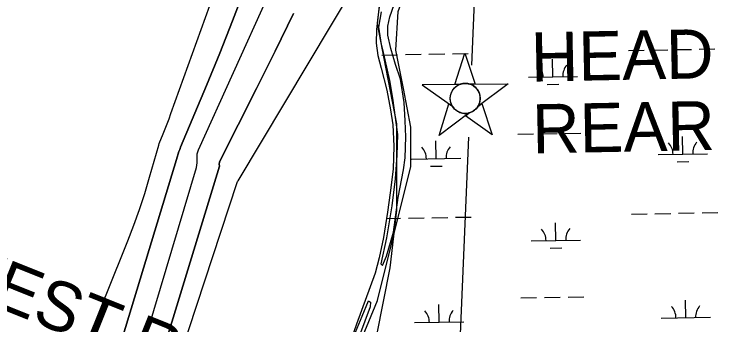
# Model space of a CAD drawing. Extents: x 3925854 to 3964121, y 224593 to 250589.
# Drawn here: x 3942841 to 3944269, y 234463 to 235095 of the extents above; entities that cross this region are included whole.
import ezdxf

# ---------------------------------------------------------------- set-up
doc = ezdxf.new("R2010")
doc.units = 0
for name, color, linetype in [('V-CHAN-NAID', 7, 'Continuous'), ('V-RIVR-EDGE', 7, 'Continuous'), ('V-RIVR-JETY', 7, 'Continuous'), ('V-RIVR-RANG', 7, 'Continuous'), ('V-RRAP-FSHR', 7, 'Continuous'), ('V-TOPO-DPTH', 7, 'Continuous'), ('V-TOPO-MAJR', 7, 'Continuous'), ('V-TOPO-MINR', 7, 'Continuous'), ('V-WETL-SWMP', 7, 'Continuous')]:
    doc.layers.add(name, color=color, linetype=linetype)

msp = doc.modelspace()

# ---------------------------------------------------------------- linework, layer by layer
at = {"layer": 'V-CHAN-NAID'}
for points in [[(3943747.738, 234951.96), (3943738.152, 234951.841), (3943758.037, 235015.724), (3943779.5, 234952.353), (3943769.913, 234952.235), (3943768.325, 234952.782), (3943766.219, 234953.361), (3943764.17, 234953.772), (3943762.129, 234954.04), (3943760.96, 234954.131), (3943759.424, 234954.183), (3943757.703, 234954.147), (3943756.334, 234954.05), (3943754.432, 234953.812), (3943753.071, 234953.567), (3943751.295, 234953.148), (3943749.773, 234952.698), (3943748.748, 234952.347)], [(3943747.738, 234951.96), (3943671.251, 234951.012), (3943733.689, 234906.82), (3943732.539, 234908.707), (3943731.697, 234910.319), (3943730.834, 234912.271), (3943730.098, 234914.311), (3943729.708, 234915.626), (3943729.315, 234917.245), (3943729.043, 234918.685), (3943728.824, 234920.279), (3943728.681, 234922.013), (3943728.638, 234923.593), (3943728.705, 234925.669), (3943728.856, 234927.29), (3943729.205, 234929.5), (3943729.649, 234931.432), (3943730.215, 234933.331), (3943730.837, 234935.022), (3943731.533, 234936.624), (3943732.317, 234938.175), (3943733.344, 234939.932), (3943734.346, 234941.422), (3943735.321, 234942.71), (3943736.301, 234943.875), (3943737.583, 234945.238), (3943738.615, 234946.223), (3943740.305, 234947.653), (3943741.5, 234948.546), (3943743.165, 234949.649), (3943744.878, 234950.628), (3943746.31, 234951.34)], [(3943769.913, 234952.235), (3943846.401, 234953.181), (3943785.077, 234907.456), (3943785.959, 234908.963), (3943786.901, 234910.829), (3943787.585, 234912.427), (3943788.286, 234914.396), (3943788.796, 234916.191), (3943789.162, 234917.838), (3943789.484, 234919.855), (3943789.639, 234921.431), (3943789.72, 234923.639), (3943789.65, 234925.7), (3943789.419, 234927.916), (3943789.118, 234929.668), (3943788.584, 234931.89), (3943787.902, 234934.017), (3943787.114, 234935.984), (3943786.438, 234937.415), (3943785.394, 234939.311), (3943784.298, 234941.012), (3943783.052, 234942.69), (3943781.761, 234944.204), (3943780.462, 234945.545), (3943778.801, 234947.045), (3943777.031, 234948.422), (3943775.325, 234949.566), (3943773.416, 234950.661), (3943771.93, 234951.394)], [(3943767.301, 234894.202), (3943705.977, 234848.477), (3943725.862, 234912.359), (3943733.689, 234906.82), (3943734.342, 234905.869), (3943735.761, 234904.037), (3943737.002, 234902.645), (3943738.497, 234901.171), (3943739.91, 234899.947), (3943741.386, 234898.82), (3943742.808, 234897.86), (3943744.506, 234896.857), (3943746.237, 234895.98), (3943748.044, 234895.204), (3943749.5, 234894.676), (3943751.138, 234894.179), (3943753.375, 234893.658), (3943754.912, 234893.401), (3943756.942, 234893.184), (3943758.481, 234893.11), (3943760.342, 234893.124), (3943762.029, 234893.235), (3943763.735, 234893.444), (3943765.631, 234893.792)], [(3943785.077, 234907.456), (3943792.763, 234913.188), (3943814.225, 234849.817), (3943759.614, 234888.471), (3943767.301, 234894.202), (3943768.957, 234894.71), (3943770.558, 234895.301), (3943772.698, 234896.257), (3943774.415, 234897.175), (3943776.259, 234898.325), (3943777.974, 234899.571), (3943779.502, 234900.846), (3943780.766, 234902.038), (3943782.122, 234903.485), (3943783.298, 234904.91), (3943784.389, 234906.404)]]:
    msp.add_lwpolyline(points, close=True, dxfattribs=at)
msp.add_circle((3943759.178, 234923.643), 30.541, dxfattribs=at)
at = {"layer": 'V-RIVR-EDGE'}
msp.add_lwpolyline([(3944040.446, 236067.646), (3944007.385, 235995.227), (3943991.642, 235945.636), (3943960.942, 235890.535), (3943855.463, 235692.957), (3943812.956, 235631.558), (3943768.875, 235583.541), (3943727.155, 235505.612), (3943670.48, 235374.156), (3943636.632, 235260.018), (3943585.466, 235124.626), (3943579.956, 235075.035), (3943597.274, 234983.724), (3943619.314, 234871.947), (3943619.314, 234696.41), (3943605.932, 234579.123), (3943578.382, 234442.157)], dxfattribs=at)
at = {"layer": 'V-RIVR-JETY'}
for points in [[(3943587.93, 235099.563), (3943582.437, 235068.37), (3943587.831, 235033.121), (3943590.822, 235022.92), (3943605.227, 234959.805), (3943611.009, 234924.162), (3943621.361, 234850.157), (3943619.631, 234807.971), (3943616.649, 234759.937), (3943610.06, 234705.306), (3943599.036, 234640.184), (3943587.395, 234587.575), (3943590.86, 234583.62), (3943598.93, 234602.665), (3943613.253, 234651.329), (3943622.404, 234722.34), (3943633.303, 234778.084), (3943637.151, 234803.047), (3943638.104, 234845.244), (3943636.584, 234878.094), (3943634.733, 234915.249), (3943627.542, 234962.635), (3943617.392, 234992.866), (3943608.047, 235025.036), (3943601.762, 235052.088), (3943601.614, 235070.461), (3943605.776, 235089.554), (3943614.705, 235114.452)], [(3943535.585, 234448.071), (3943549.698, 234480.714), (3943562.616, 234511.809), (3943566.493, 234509.413), (3943565.973, 234499.648), (3943543.703, 234441.319)]]:
    msp.add_lwpolyline(points, dxfattribs=at)
at = {"layer": 'V-RIVR-RANG'}
for points in [[(3943812.557, 235958.749), (3943771.737, 234990.891)], [(3943765.567, 234844.599), (3943658.865, 232314.647)]]:
    msp.add_lwpolyline(points, dxfattribs=at)
at = {"layer": 'V-RRAP-FSHR'}
msp.add_lwpolyline([(3943550.3, 234438.974), (3943580.758, 234512.837), (3943648.153, 234785.105), (3943648.444, 234864.923), (3943633.272, 234943.444), (3943617.876, 235021.948), (3943622.994, 235100.327), (3943650.171, 235175.566), (3943678.906, 235250.224), (3943708.387, 235324.593), (3943738.82, 235398.878), (3943769.606, 235472.399), (3943805.37, 235543.862), (3943853.205, 235607.915), (3943894.849, 235676.646), (3943933.18, 235746.524), (3943970.3, 235817.305), (3944005.82, 235888.983), (3944041.119, 235960.773), (3944076.417, 236032.566), (3944110.874, 236104.758)], dxfattribs=at)
at = {"layer": 'V-TOPO-DPTH'}
for points in [[(3943310.805, 235147.024), (3943285.653, 235081.057), (3943259.501, 235015.481), (3943232.683, 234950.164), (3943179.881, 234824.293), (3943178.983, 234822.099), (3943178.111, 234819.895), (3943176.468, 234815.449), (3943174.989, 234810.947), (3943174.33, 234808.672), (3943173.711, 234806.385), (3942881.483, 233843.977)], [(3943310.805, 235147.024), (3943285.653, 235081.057), (3943259.501, 235015.481), (3943232.683, 234950.164), (3943179.881, 234824.293), (3943178.983, 234822.099), (3943178.111, 234819.895), (3943176.468, 234815.449), (3943174.989, 234810.947), (3943174.33, 234808.672), (3943173.711, 234806.385), (3942881.483, 233843.977)], [(3942928.961, 233833.411), (3943212.465, 234783.374), (3943213.2, 234787.903), (3943213.669, 234792.448), (3943213.741, 234797.016), (3943213.547, 234801.6), (3943213.509, 234806.135), (3943213.923, 234810.593), (3943215.016, 234814.935), (3943216.56, 234819.199), (3943359.149, 235134.282)], [(3942928.961, 233833.411), (3943212.465, 234783.374), (3943213.2, 234787.903), (3943213.669, 234792.448), (3943213.741, 234797.016), (3943213.547, 234801.6), (3943213.509, 234806.135), (3943213.923, 234810.593), (3943215.016, 234814.935), (3943216.56, 234819.199), (3943359.149, 235134.282)], [(3943409.481, 235096.015), (3943372.545, 235019.535), (3943334.705, 234943.483), (3943259.636, 234795.889), (3943258.889, 234793.924), (3943258.397, 234789.875), (3943259.115, 234785.669), (3942961.537, 233812.001)]]:
    msp.add_lwpolyline(points, dxfattribs=at)
at = {"layer": 'V-TOPO-MAJR'}
msp.add_lwpolyline([(3942776.226, 233899.699), (3943062.837, 234610.469), (3943072.36, 234633.768), (3943084.797, 234665.73), (3943096.506, 234697.943), (3943107.122, 234730.532), (3943117.009, 234763.373), (3943135.472, 234828.671), (3943135.583, 234829.05), (3943135.951, 234830.176), (3943136.224, 234830.917), (3943136.366, 234831.285), (3943136.513, 234831.652), (3943144.552, 234851.433), (3943148.658, 234861.714), (3943152.682, 234872.026), (3943156.581, 234882.385), (3943160.398, 234892.777), (3943486.229, 235796.554)], dxfattribs=at)
at = {"layer": 'V-TOPO-MINR'}
for points in [[(3943812.557, 235958.749), (3943771.737, 234990.891)], [(3943812.557, 235958.749), (3943771.737, 234990.891)], [(3942982.448, 233802.833), (3943295.161, 234752.419), (3943296.059, 234754.917), (3943297.381, 234756.189), (3943629.757, 235311.766), (3943642.011, 235333.225), (3943654.509, 235354.538), (3943667.373, 235375.633), (3943680.48, 235396.581), (3943707.06, 235438.26)], [(3942881.483, 233843.977), (3943173.711, 234806.385), (3943174.33, 234808.672), (3943174.989, 234810.947), (3943176.468, 234815.449), (3943178.111, 234819.895), (3943178.983, 234822.099), (3943179.881, 234824.293), (3943232.683, 234950.164), (3943259.501, 235015.481), (3943285.653, 235081.057), (3943310.805, 235147.024)], [(3942928.961, 233833.411), (3943212.465, 234783.374), (3943213.2, 234787.903), (3943213.669, 234792.448), (3943213.741, 234797.016), (3943213.547, 234801.6), (3943213.509, 234806.135), (3943213.923, 234810.593), (3943215.016, 234814.935), (3943216.56, 234819.199), (3943359.149, 235134.282)], [(3942961.537, 233812.001), (3943259.115, 234785.669), (3943258.397, 234789.875), (3943258.889, 234793.924), (3943259.636, 234795.889), (3943334.705, 234943.483), (3943372.545, 235019.535), (3943409.481, 235096.015)], [(3943765.567, 234844.599), (3943658.865, 232314.647)], [(3943765.567, 234844.599), (3943658.865, 232314.647)]]:
    msp.add_lwpolyline(points, dxfattribs=at)
at = {"layer": 'V-WETL-SWMP'}
for p, q in [((3943685.364, 235013.592), (3943717.359, 235014.174)), ((3943733.356, 235014.464), (3943765.351, 235015.046)), ((3944091.205, 235020.971), (3944123.2, 235021.553)), ((3944139.197, 235021.844), (3944171.192, 235022.426)), ((3944187.189, 235022.716), (3944219.184, 235023.298)), ((3944235.181, 235023.589), (3944267.176, 235024.171)), ((3943589.38, 235011.846), (3943621.374, 235012.428)), ((3943637.372, 235012.719), (3943669.367, 235013.301)), ((3943937.561, 234967.427), (3943936.906, 235003.421)), ((3943887.569, 234966.518), (3943987.553, 234968.336)), ((3943925.843, 234951.78), (3943949.839, 234952.217)), ((3943866.264, 234850.68), (3943898.258, 234851.261)), ((3943914.256, 234851.552), (3943946.25, 234852.134)), ((3943962.248, 234852.425), (3943994.242, 234853.007)), ((3944201.896, 234810.345), (3944201.242, 234846.339)), ((3943700.071, 234801.22), (3943699.417, 234837.214)), ((3943650.08, 234800.311), (3943750.063, 234802.129)), ((3944151.905, 234809.436), (3944251.888, 234811.254)), ((3943688.354, 234785.573), (3943712.35, 234786.01)), ((3944190.179, 234794.698), (3944214.175, 234795.134)), ((3944097.253, 234688.351), (3944129.248, 234688.933)), ((3944145.245, 234689.224), (3944177.24, 234689.806)), ((3944193.237, 234690.096), (3944225.232, 234690.678)), ((3944241.229, 234690.969), (3944273.224, 234691.551)), ((3943598.873, 234679.289), (3943627.423, 234679.808)), ((3943643.42, 234680.099), (3943675.415, 234680.681)), ((3943691.412, 234680.972), (3943723.407, 234681.553)), ((3943739.404, 234681.844), (3943771.399, 234682.426)), ((3943943.609, 234634.807), (3943942.954, 234670.801)), ((3943893.617, 234633.898), (3943993.601, 234635.716)), ((3943931.891, 234619.16), (3943955.887, 234619.597)), ((3943872.312, 234518.06), (3943904.306, 234518.641)), ((3943920.304, 234518.932), (3943952.298, 234519.514)), ((3943968.296, 234519.805), (3944000.29, 234520.387)), ((3943706.119, 234468.6), (3943705.465, 234504.594)), ((3944207.944, 234477.725), (3944207.29, 234513.719)), ((3944157.953, 234476.816), (3944257.936, 234478.634)), ((3943656.128, 234467.691), (3943756.111, 234469.509))]:
    msp.add_line(p, q, dxfattribs=at)
msp.add_lwpolyline([(3943584.79, 235114.478), (3943581.137, 235089.095), (3943578.865, 235063.694), (3943577.946, 235036.064), (3943581.205, 235010.867), (3943587.77, 234984.796), (3943599.344, 234940.415), (3943606.831, 234900.511), (3943611.679, 234870.04), (3943614.14, 234826.333), (3943612.419, 234779.917), (3943606.527, 234731.621), (3943601.032, 234692.442), (3943592.611, 234641.139), (3943584.323, 234599.786), (3943575.887, 234568.109), (3943537.755, 234464.956), (3943527.69, 234435.513)], dxfattribs=at)
for centre, start, end in [((3943882.318, 234966.897), 0.269879, 41.813537), ((3943992.786, 234968.906), 140.269876, 181.813534), ((3944146.654, 234809.815), 0.269879, 41.813537), ((3944257.121, 234811.824), 140.269876, 181.813534), ((3943644.829, 234800.69), 0.269879, 41.813537), ((3943755.296, 234802.699), 140.269876, 181.813534), ((3943888.366, 234634.277), 0.269879, 41.813537), ((3943998.834, 234636.286), 140.269876, 181.813534), ((3944152.702, 234477.195), 0.269879, 41.813537), ((3944263.17, 234479.204), 140.269876, 181.813534), ((3943650.877, 234468.07), 0.269879, 41.813537), ((3943761.344, 234470.079), 140.269876, 181.813534)]:
    msp.add_arc(centre, 35.246, start, end, dxfattribs=at)

# ---------------------------------------------------------------- texts
at = {"layer": 'V-CHAN-NAID'}
for s, rotation, p in [('HEAD RANGE', 1.11601, (3943893.633, 234957.605)), ('HEAD RANGE WEST REAR', 338.11001, (3941819.178, 234895.357)), ('REAR', 1.11601, (3943896.289, 234811.579))]:
    msp.add_text(s, height=100, rotation=rotation, dxfattribs=at).set_placement(p)

doc.saveas('drawing.dxf')
